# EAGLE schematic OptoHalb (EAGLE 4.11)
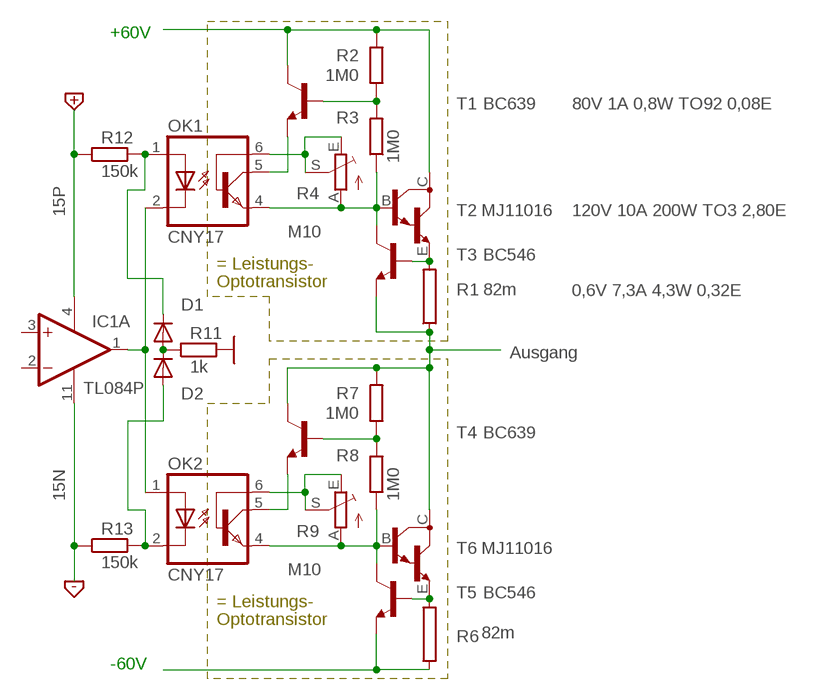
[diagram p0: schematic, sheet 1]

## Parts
D1  DIODE-D-2.5  [D-2.5]
D2  DIODE-D-2.5  [D-2.5]
IC1  TL084P  [DIL14]
OK1  CNY17  [DIL06]
OK2  CNY17  [DIL06]
R1  82m  RKH208-8  [KH208-8]
R2  1M0  R-EU_0207/10  [0207/10]
R3  1M0  R-EU_0207/10  [0207/10]
R4  M10  TRIM_EU-CA9V  [CA9V]
R6  82m  RKH208-8  [KH208-8]
R7  1M0  R-EU_0207/10  [0207/10]
R8  1M0  R-EU_0207/10  [0207/10]
R9  M10  TRIM_EU-CA9V  [CA9V]
R11  1k  R-EU_0207/10  [0207/10]
R12  150k  R-EU_0207/10  [0207/10]
R13  150k  R-EU_0207/10  [0207/10]
T1  BC639  2N4124-NPN-TO92-CBE  [TO92-CBE]
T2  MJ11016  MJ10007  [TO3]
T3  BC546  2N4124-NPN-TO92-CBE  [TO92-CBE]
T4  BC639  2N4124-NPN-TO92-CBE  [TO92-CBE]
T5  BC546  2N4124-NPN-TO92-CBE  [TO92-CBE]
T6  MJ11016  MJ10007  [TO3]

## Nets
15N: IC1.11(P:V-) R13.1
15P: IC1.4(P:V+) R12.1
60N: R6.1 T5.E
60P: R2.2 T1.C T2.C
GND: R11.2
N$1: R1.1 R7.2 T3.E T4.C T6.C
N$2: R6.2 T5.B T6.E
N$3: R1.2 T2.E T3.B
N$4: R2.1 R3.2 T1.B
N$5: OK1.6(BAS) R4.E R4.S
N$6: OK1.4(EMI) R3.1 R4.A T2.B T3.C
N$7: OK1.5(COL) T1.E
N$8: R7.1 R8.2 T4.B
N$9: D1.C OK1.1(A) R12.2
N$10: OK2.6(BAS) R9.E R9.S
N$11: OK2.4(EMI) R8.1 R9.A T5.C T6.B
N$12: OK2.5(COL) T4.E
N$13: IC1.1(A:OUT) OK1.2(C) OK2.1(A)
N$14: D2.A OK2.2(C) R13.2
N$15: D1.A D2.C R11.1
Unconnected: IC1.2(A:-IN) IC1.3(A:+IN) IC1.5(B:+IN) IC1.6(B:-IN) IC1.7(B:OUT) IC1.8(C:OUT) IC1.9(C:-IN) IC1.10(C:+IN) IC1.12(D:+IN) IC1.13(D:-IN) IC1.14(D:OUT) T2.C/(C) T6.C/(C)

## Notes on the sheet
- +60V
- 80V 1A 0,8W TO92 0,08E
- 120V 10A 200W TO3 2,80E
- = Leistungs-
- Optotransistor
- 0,6V 7,3A 4,3W 0,32E
- Ausgang
- = Leistungs-
- Optotransistor
- -60V

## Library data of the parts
D1 D2 = diode:DIODE-: DIODE
IC1 = linear:TL084: OP AMP
OK1 OK2 = optocoupler:CNY17: SIEMENS OPTO COUPLER
R1 R6 = resistor-power:R: Power Resitor
R2 R3 R7 R8 R11-R13 = rcl:R-EU_: RESISTOR, European symbol
R4 R9 = pot:TRIM_EU-: POTENTIOMETER
T1 T3-T5 = transistor:*-NPN-: NPN Transistror
T2 T6 = transistor-npn:MJ10007*: NPN Darlington Transistor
